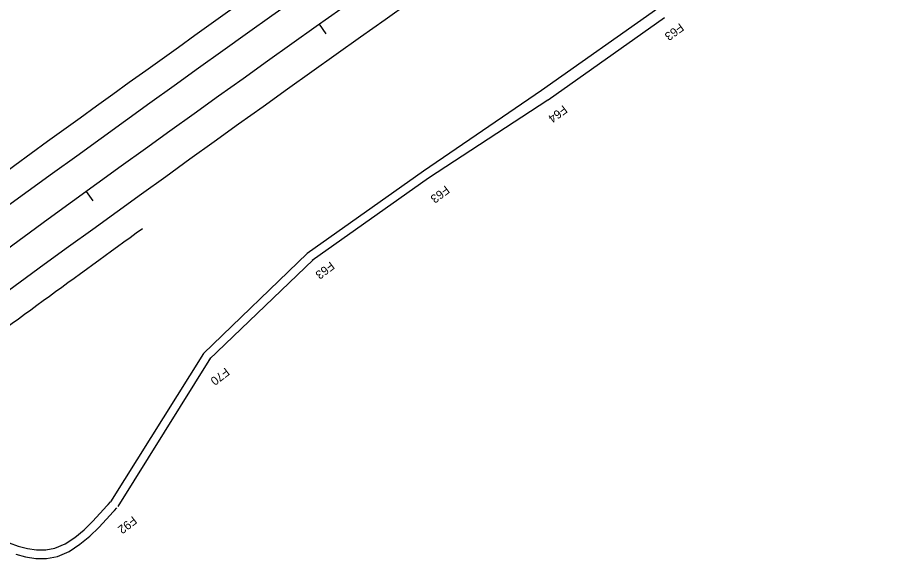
# Model space of a CAD drawing. Extents: x 1469024 to 1473560, y 1105695 to 1109739.
# Drawn here: x 1471173.7 to 1471479.1, y 1107626.8 to 1107815.4 of the extents above; entities that cross this region are included whole.
import ezdxf

# ---------------------------------------------------------------- set-up
doc = ezdxf.new("R2010")
doc.units = 0
for name, color, linetype in [('RD_HC_CL_Rel', 7, 'Continuous'), ('RD_HC_Data_Tic_Rel', 7, 'Continuous'), ('RD_PD_CstnLmt', 7, 'Continuous'), ('RD_PD_CstnLmt_TX', 7, 'Continuous'), ('RD_PD_DR_ErosCtrl', 7, 'Continuous'), ('RD_PD_Final_TrvlWay', 7, 'Continuous'), ('RD_PD_GR', 7, 'Continuous')]:
    doc.layers.add(name, color=color, linetype=linetype)

msp = doc.modelspace()

# ---------------------------------------------------------------- linework, layer by layer
at = {"layer": 'RD_HC_CL_Rel'}
msp.add_arc((1477943.58, 1098441.09), 11500, 123.079489, 126.41418, dxfattribs=at)
at = {"layer": 'RD_HC_Data_Tic_Rel'}
for p, q in [((1471278.94, 1107813), (1471281.26, 1107809.74)), ((1471197.7, 1107754.69), (1471200.05, 1107751.45))]:
    msp.add_line(p, q, dxfattribs=at)
at = {"layer": 'RD_PD_CstnLmt'}
for p, q in [((1471397.03, 1107818.54), (1471356.39, 1107789.89)), ((1471356.39, 1107789.89), (1471315.3, 1107761.86)), ((1471315.3, 1107761.86), (1471274.76, 1107733.07)), ((1471274.76, 1107733.07), (1471238.53, 1107698.32)), ((1471238.53, 1107698.32), (1471206.2, 1107646.55))]:
    msp.add_line(p, q, dxfattribs=at)
msp.add_lwpolyline([(1471170.88, 1107632.22), (1471173.99, 1107631.14), (1471177.17, 1107630.3), (1471180.39, 1107629.82), (1471183.6, 1107629.83), (1471186.77, 1107630.43), (1471190.32, 1107631.95), (1471193.73, 1107634.18), (1471196.94, 1107636.86), (1471199.9, 1107639.75), (1471202.57, 1107642.6), (1471204.89, 1107645.15), (1471205.34, 1107645.63), (1471206.2, 1107646.55)], dxfattribs=at)
at = {"layer": 'RD_PD_DR_ErosCtrl'}
for p, q in [((1471399.33, 1107815.27), (1471358.69, 1107786.62)), ((1471358.64, 1107786.59), (1471317.04, 1107759.42)), ((1471317.04, 1107759.42), (1471276.5, 1107730.63)), ((1471276.84, 1107730.91), (1471240.6, 1107696.16)), ((1471241.07, 1107696.73), (1471208.75, 1107644.96))]:
    msp.add_line(p, q, dxfattribs=at)
msp.add_lwpolyline([(1471173.12, 1107628.27), (1471176.57, 1107627.36), (1471180.17, 1107626.82), (1471183.88, 1107626.83), (1471187.65, 1107627.54), (1471191.75, 1107629.3), (1471195.52, 1107631.77), (1471198.95, 1107634.64), (1471202.04, 1107637.65), (1471204.77, 1107640.56), (1471207.1, 1107643.12), (1471207.53, 1107643.58), (1471208.39, 1107644.5)], dxfattribs=at)
at = {"layer": 'RD_PD_Final_TrvlWay'}
for radius in [11512, 11488]:
    msp.add_arc((1477943.58, 1098441.09), radius, 123.079489, 126.41418, dxfattribs=at)
at = {"layer": 'RD_PD_GR'}
for radius, start, end in [(11522, 124.172166, 126.408649), (11478, 125.874656, 126.301954)]:
    msp.add_arc((1477943.58, 1098441.09), radius, start, end, dxfattribs=at)

# ---------------------------------------------------------------- texts
at = {"layer": 'RD_PD_CstnLmt_TX'}
for s, rotation, p in [('F63', 216.431, (1471404.62, 1107813.58)), ('F64', 216.6801, (1471364, 1107784.96)), ('F63', 216.9292, (1471322.94, 1107756.97)), ('F63', 217.1783, (1471282.8, 1107730.49)), ('F70', 217.4274, (1471246.2, 1107693.5)), ('F70', 217.4274, (1471246.2, 1107693.5)), ('F92', 217.6765, (1471213.9, 1107641.76)), ('F92', 217.6765, (1471213.9, 1107641.76))]:
    msp.add_text(s, height=3, rotation=rotation, dxfattribs=at).set_placement(p)

doc.saveas('drawing.dxf')
